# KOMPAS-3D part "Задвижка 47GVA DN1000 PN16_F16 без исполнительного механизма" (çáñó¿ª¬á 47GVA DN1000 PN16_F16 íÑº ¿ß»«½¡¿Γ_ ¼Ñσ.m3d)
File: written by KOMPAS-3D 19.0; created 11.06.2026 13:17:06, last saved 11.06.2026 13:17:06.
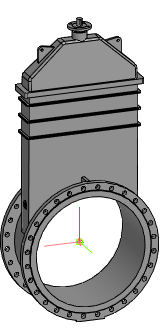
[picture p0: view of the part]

Document properties: Автор: Евгений; Полное имя файла: Z:\3.Личные\kachalov\001_3d для проектировщиков\2.2 Тип 47GVA, 47GVA.Z\_stp\_stp_Задвижка 47GVA DN40-DN1000 без исп.мех\Задвижка 47GVA DN1000 PN16_F16 без исполнит_ мех.m3d

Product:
- Part/product: Задвижка 47GVA DN1000 PN16_F16 без исполнительного механизма

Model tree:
1. Операция без истории:1  (labels: Задвижка 47GVA DN1000 PN16_F16 без исполнительного механизма)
